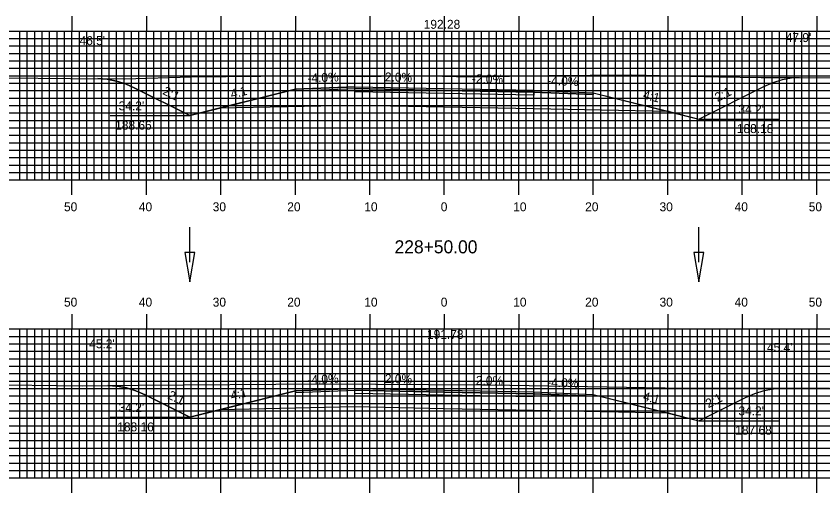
# Model space of a CAD drawing. Extents: x 1798781 to 1799124, y 442591 to 442811.
# Drawn here: x 1798889.5 to 1798997.8, y 442686.7 to 442750.7 of the extents above; entities that cross this region are included whole.
import ezdxf

# ---------------------------------------------------------------- set-up
doc = ezdxf.new("R2010")
doc.units = 0
for name, color, linetype in [('ANNOTATION', 7, 'Continuous'), ('D_Drainage_Ditch_Line', 7, 'Continuous'), ('D_Roadway_Centerline', 7, 'Continuous'), ('D_Roadway_Centerline_Text', 7, 'Continuous'), ('D_Roadway_Edge_Shoulder', 7, 'Continuous'), ('D_Roadway_Edge_TW', 7, 'Continuous'), ('D_Roadway_Pavement', 7, 'Continuous'), ('D_Roadway_SlopeLines', 7, 'Continuous'), ('D_Roadway_SubGrade', 7, 'Continuous'), ('D_Text_Standard', 7, 'Continuous'), ('H_V ANNOTATION', 7, 'Continuous'), ('MAJOR', 7, 'Continuous'), ('MINOR', 7, 'Continuous'), ('PDRAIN', 7, 'Continuous'), ('S_Roadway_Centerline', 7, 'Continuous')]:
    doc.layers.add(name, color=color, linetype=linetype)

msp = doc.modelspace()

# ---------------------------------------------------------------- linework, layer by layer
at = {"layer": 'D_Drainage_Ditch_Line'}
for p, q in [((1798912.81, 442717.63), (1798912.81, 442722.33)), ((1798981.16, 442717.63), (1798981.16, 442722.33))]:
    msp.add_line(p, q, dxfattribs=at)
for points in [[(1798913.47, 442718.94), (1798912.15, 442718.94), (1798912.81, 442715)], [(1798981.81, 442718.94), (1798980.5, 442718.94), (1798981.16, 442715)]]:
    msp.add_lwpolyline(points, close=True, dxfattribs=at)
at = {"layer": 'D_Roadway_Centerline'}
for points in [[(1798900.44, 442742.28), (1798901.69, 442742.19), (1798902.94, 442741.95), (1798904.19, 442741.56), (1798905.44, 442741.01), (1798912.81, 442737.33), (1798916.81, 442738.33), (1798926.98, 442740.87), (1798934.98, 442741.19), (1798946.98, 442740.95), (1798958.98, 442740.71), (1798966.98, 442740.39), (1798977.16, 442737.85), (1798981.16, 442736.85), (1798989.87, 442741.2), (1798991.12, 442741.75), (1798992.37, 442742.14), (1798993.62, 442742.37), (1798994.87, 442742.45)], [(1798901.79, 442701.06), (1798903.04, 442700.99), (1798904.29, 442700.77), (1798905.54, 442700.38), (1798906.79, 442699.84), (1798912.81, 442696.83), (1798916.81, 442697.83), (1798926.98, 442700.37), (1798934.98, 442700.69), (1798946.98, 442700.45), (1798958.98, 442700.21), (1798966.98, 442699.89), (1798977.16, 442697.35), (1798981.16, 442696.35), (1798987.41, 442699.47), (1798988.66, 442700.02), (1798989.91, 442700.41), (1798991.16, 442700.64), (1798992.41, 442700.72)]]:
    msp.add_lwpolyline(points, dxfattribs=at)
at = {"layer": 'D_Roadway_Edge_Shoulder'}
for points in [[(1798934.98, 442741.19), (1798926.98, 442740.87), (1798926.98, 442740.62), (1798934.98, 442740.94)], [(1798958.98, 442740.71), (1798966.98, 442740.39), (1798966.98, 442740.14), (1798958.98, 442740.46)], [(1798934.98, 442700.69), (1798926.98, 442700.37), (1798926.98, 442700.12), (1798934.98, 442700.44)], [(1798958.98, 442700.21), (1798966.98, 442699.89), (1798966.98, 442699.64), (1798958.98, 442699.96)]]:
    msp.add_lwpolyline(points, close=True, dxfattribs=at)
at = {"layer": 'D_Roadway_Edge_TW'}
for points in [[(1798934.98, 442740.94), (1798934.98, 442741.19), (1798946.98, 442740.95), (1798958.98, 442740.71), (1798958.98, 442740.46), (1798946.98, 442740.7)], [(1798934.98, 442700.44), (1798934.98, 442700.69), (1798946.98, 442700.45), (1798958.98, 442700.21), (1798958.98, 442699.96), (1798946.98, 442700.2)]]:
    msp.add_lwpolyline(points, close=True, dxfattribs=at)
at = {"layer": 'D_Roadway_Pavement'}
for points in [[(1798934.98, 442740.52), (1798934.98, 442740.94), (1798946.98, 442740.7), (1798958.98, 442740.46), (1798958.98, 442740.04), (1798946.98, 442740.28)], [(1798934.98, 442700.02), (1798934.98, 442700.44), (1798946.98, 442700.2), (1798958.98, 442699.96), (1798958.98, 442699.54), (1798946.98, 442699.78)]]:
    msp.add_lwpolyline(points, close=True, dxfattribs=at)
at = {"layer": 'D_Roadway_SlopeLines'}
for points in [[(1798912.81, 442737.33), (1798905.44, 442741.01), (1798904.19, 442741.56), (1798902.94, 442741.95), (1798901.69, 442742.19), (1798900.44, 442742.28)], [(1798981.16, 442736.85), (1798989.87, 442741.2), (1798991.12, 442741.75), (1798992.37, 442742.14), (1798993.62, 442742.37), (1798994.87, 442742.45)], [(1798926.98, 442740.87), (1798912.81, 442737.33)], [(1798966.98, 442740.39), (1798981.16, 442736.85)], [(1798912.81, 442696.83), (1798906.79, 442699.84), (1798905.54, 442700.38), (1798904.29, 442700.77), (1798903.04, 442700.99), (1798901.79, 442701.06)], [(1798926.98, 442700.37), (1798912.81, 442696.83)], [(1798981.16, 442696.35), (1798987.41, 442699.47), (1798988.66, 442700.02), (1798989.91, 442700.41), (1798991.16, 442700.64), (1798992.41, 442700.72)], [(1798966.98, 442699.89), (1798981.16, 442696.35)]]:
    msp.add_lwpolyline(points, dxfattribs=at)
at = {"layer": 'D_Roadway_SubGrade'}
for points in [[(1798934.98, 442738.69), (1798916.81, 442738.33), (1798926.98, 442740.87), (1798926.98, 442740.62), (1798934.98, 442740.94), (1798946.98, 442740.7), (1798958.98, 442740.46), (1798966.98, 442740.14), (1798966.98, 442740.39), (1798977.16, 442737.85), (1798958.98, 442738.21), (1798946.98, 442738.45)], [(1798934.98, 442698.19), (1798916.81, 442697.83), (1798926.98, 442700.37), (1798926.98, 442700.12), (1798934.98, 442700.44), (1798946.98, 442700.2), (1798958.98, 442699.96), (1798966.98, 442699.64), (1798966.98, 442699.89), (1798977.16, 442697.35), (1798958.98, 442697.71), (1798946.98, 442697.95)]]:
    msp.add_lwpolyline(points, close=True, dxfattribs=at)
at = {"layer": 'MAJOR'}
for p, q in [((1798896.98, 442750.67), (1798896.98, 442748.67)), ((1798906.98, 442750.67), (1798906.98, 442748.67)), ((1798916.98, 442750.67), (1798916.98, 442748.67)), ((1798926.98, 442750.67), (1798926.98, 442748.67)), ((1798936.98, 442750.67), (1798936.98, 442748.67)), ((1798946.98, 442750.67), (1798946.98, 442748.67)), ((1798956.98, 442750.67), (1798956.98, 442748.67)), ((1798966.98, 442750.67), (1798966.98, 442748.67)), ((1798976.98, 442750.67), (1798976.98, 442748.67)), ((1798986.98, 442750.67), (1798986.98, 442748.67)), ((1798996.98, 442750.67), (1798996.98, 442748.67)), ((1798806.98, 442748.67), (1799086.98, 442748.67)), ((1798806.98, 442748.67), (1799086.98, 442748.67)), ((1798896.98, 442728.67), (1798896.98, 442748.67)), ((1798906.98, 442728.67), (1798906.98, 442748.67)), ((1798916.98, 442728.67), (1798916.98, 442748.67)), ((1798926.98, 442728.67), (1798926.98, 442748.67)), ((1798936.98, 442728.67), (1798936.98, 442748.67)), ((1798946.98, 442728.67), (1798946.98, 442748.67)), ((1798956.98, 442728.67), (1798956.98, 442748.67)), ((1798966.98, 442728.67), (1798966.98, 442748.67)), ((1798976.98, 442728.67), (1798976.98, 442748.67)), ((1798986.98, 442728.67), (1798986.98, 442748.67)), ((1798996.98, 442728.67), (1798996.98, 442748.67)), ((1798806.98, 442743.67), (1799086.98, 442743.67)), ((1798806.98, 442738.67), (1799086.98, 442738.67)), ((1798806.98, 442733.67), (1799086.98, 442733.67)), ((1798806.98, 442728.67), (1799086.98, 442728.67)), ((1798806.98, 442728.67), (1799086.98, 442728.67)), ((1798896.98, 442726.66), (1798896.98, 442728.67)), ((1798906.98, 442726.66), (1798906.98, 442728.67)), ((1798916.98, 442726.66), (1798916.98, 442728.67)), ((1798926.98, 442726.66), (1798926.98, 442728.67)), ((1798936.98, 442726.66), (1798936.98, 442728.67)), ((1798946.98, 442726.66), (1798946.98, 442728.67)), ((1798956.98, 442726.66), (1798956.98, 442728.67)), ((1798966.98, 442726.66), (1798966.98, 442728.67)), ((1798976.98, 442726.66), (1798976.98, 442728.67)), ((1798986.98, 442726.66), (1798986.98, 442728.67)), ((1798996.98, 442726.66), (1798996.98, 442728.67)), ((1798896.98, 442710.67), (1798896.98, 442708.67)), ((1798906.98, 442710.67), (1798906.98, 442708.67)), ((1798916.98, 442710.67), (1798916.98, 442708.67)), ((1798926.98, 442710.67), (1798926.98, 442708.67)), ((1798936.98, 442710.67), (1798936.98, 442708.67)), ((1798946.98, 442710.67), (1798946.98, 442708.67)), ((1798956.98, 442710.67), (1798956.98, 442708.67)), ((1798966.98, 442710.67), (1798966.98, 442708.67)), ((1798976.98, 442710.67), (1798976.98, 442708.67)), ((1798986.98, 442710.67), (1798986.98, 442708.67)), ((1798996.98, 442710.67), (1798996.98, 442708.67)), ((1798806.98, 442708.67), (1799086.98, 442708.67)), ((1798806.98, 442708.67), (1799086.98, 442708.67)), ((1798896.98, 442688.67), (1798896.98, 442708.67)), ((1798906.98, 442688.67), (1798906.98, 442708.67)), ((1798916.98, 442688.67), (1798916.98, 442708.67)), ((1798926.98, 442688.67), (1798926.98, 442708.67)), ((1798936.98, 442688.67), (1798936.98, 442708.67)), ((1798946.98, 442688.67), (1798946.98, 442708.67)), ((1798956.98, 442688.67), (1798956.98, 442708.67)), ((1798966.98, 442688.67), (1798966.98, 442708.67)), ((1798976.98, 442688.67), (1798976.98, 442708.67)), ((1798986.98, 442688.67), (1798986.98, 442708.67)), ((1798996.98, 442688.67), (1798996.98, 442708.67)), ((1798806.98, 442703.67), (1799086.98, 442703.67)), ((1798806.98, 442698.67), (1799086.98, 442698.67)), ((1798806.98, 442693.67), (1799086.98, 442693.67)), ((1798806.98, 442688.67), (1799086.98, 442688.67)), ((1798806.98, 442688.67), (1799086.98, 442688.67)), ((1798896.98, 442686.66), (1798896.98, 442688.67)), ((1798906.98, 442686.66), (1798906.98, 442688.67)), ((1798916.98, 442686.66), (1798916.98, 442688.67)), ((1798926.98, 442686.66), (1798926.98, 442688.67)), ((1798936.98, 442686.66), (1798936.98, 442688.67)), ((1798946.98, 442686.66), (1798946.98, 442688.67)), ((1798956.98, 442686.66), (1798956.98, 442688.67)), ((1798966.98, 442686.66), (1798966.98, 442688.67)), ((1798976.98, 442686.66), (1798976.98, 442688.67)), ((1798986.98, 442686.66), (1798986.98, 442688.67)), ((1798996.98, 442686.66), (1798996.98, 442688.67))]:
    msp.add_line(p, q, dxfattribs=at)
at = {"layer": 'MINOR'}
for p, q in [((1798889.98, 442728.67), (1798889.98, 442748.67)), ((1798890.98, 442728.67), (1798890.98, 442748.67)), ((1798891.98, 442728.67), (1798891.98, 442748.67)), ((1798892.98, 442728.67), (1798892.98, 442748.67)), ((1798893.98, 442728.67), (1798893.98, 442748.67)), ((1798894.98, 442728.67), (1798894.98, 442748.67)), ((1798895.98, 442728.67), (1798895.98, 442748.67)), ((1798897.98, 442728.67), (1798897.98, 442748.67)), ((1798898.98, 442728.67), (1798898.98, 442748.67)), ((1798899.98, 442728.67), (1798899.98, 442748.67)), ((1798900.98, 442728.67), (1798900.98, 442748.67)), ((1798901.98, 442728.67), (1798901.98, 442748.67)), ((1798902.98, 442728.67), (1798902.98, 442748.67)), ((1798903.98, 442728.67), (1798903.98, 442748.67)), ((1798904.98, 442728.67), (1798904.98, 442748.67)), ((1798905.98, 442728.67), (1798905.98, 442748.67)), ((1798907.98, 442728.67), (1798907.98, 442748.67)), ((1798908.98, 442728.67), (1798908.98, 442748.67)), ((1798909.98, 442728.67), (1798909.98, 442748.67)), ((1798910.98, 442728.67), (1798910.98, 442748.67)), ((1798911.98, 442728.67), (1798911.98, 442748.67)), ((1798912.98, 442728.67), (1798912.98, 442748.67)), ((1798913.98, 442728.67), (1798913.98, 442748.67)), ((1798914.98, 442728.67), (1798914.98, 442748.67)), ((1798915.98, 442728.67), (1798915.98, 442748.67)), ((1798917.98, 442728.67), (1798917.98, 442748.67)), ((1798918.98, 442728.67), (1798918.98, 442748.67)), ((1798919.98, 442728.67), (1798919.98, 442748.67)), ((1798920.98, 442728.67), (1798920.98, 442748.67)), ((1798921.98, 442728.67), (1798921.98, 442748.67)), ((1798922.98, 442728.67), (1798922.98, 442748.67)), ((1798923.98, 442728.67), (1798923.98, 442748.67)), ((1798924.98, 442728.67), (1798924.98, 442748.67)), ((1798925.98, 442728.67), (1798925.98, 442748.67)), ((1798927.98, 442728.67), (1798927.98, 442748.67)), ((1798928.98, 442728.67), (1798928.98, 442748.67)), ((1798929.98, 442728.67), (1798929.98, 442748.67)), ((1798930.98, 442728.67), (1798930.98, 442748.67)), ((1798931.98, 442728.67), (1798931.98, 442748.67)), ((1798932.98, 442728.67), (1798932.98, 442748.67)), ((1798933.98, 442728.67), (1798933.98, 442748.67)), ((1798934.98, 442728.67), (1798934.98, 442748.67)), ((1798935.98, 442728.67), (1798935.98, 442748.67)), ((1798937.98, 442728.67), (1798937.98, 442748.67)), ((1798938.98, 442728.67), (1798938.98, 442748.67)), ((1798939.98, 442728.67), (1798939.98, 442748.67)), ((1798940.98, 442728.67), (1798940.98, 442748.67)), ((1798941.98, 442728.67), (1798941.98, 442748.67)), ((1798942.98, 442728.67), (1798942.98, 442748.67)), ((1798943.98, 442728.67), (1798943.98, 442748.67)), ((1798944.98, 442728.67), (1798944.98, 442748.67)), ((1798945.98, 442728.67), (1798945.98, 442748.67)), ((1798947.98, 442728.67), (1798947.98, 442748.67)), ((1798948.98, 442728.67), (1798948.98, 442748.67)), ((1798949.98, 442728.67), (1798949.98, 442748.67)), ((1798950.98, 442728.67), (1798950.98, 442748.67)), ((1798951.98, 442728.67), (1798951.98, 442748.67)), ((1798952.98, 442728.67), (1798952.98, 442748.67)), ((1798953.98, 442728.67), (1798953.98, 442748.67)), ((1798954.98, 442728.67), (1798954.98, 442748.67)), ((1798955.98, 442728.67), (1798955.98, 442748.67)), ((1798957.98, 442728.67), (1798957.98, 442748.67)), ((1798958.98, 442728.67), (1798958.98, 442748.67)), ((1798959.98, 442728.67), (1798959.98, 442748.67)), ((1798960.98, 442728.67), (1798960.98, 442748.67)), ((1798961.98, 442728.67), (1798961.98, 442748.67)), ((1798962.98, 442728.67), (1798962.98, 442748.67)), ((1798963.98, 442728.67), (1798963.98, 442748.67)), ((1798964.98, 442728.67), (1798964.98, 442748.67)), ((1798965.98, 442728.67), (1798965.98, 442748.67)), ((1798967.98, 442728.67), (1798967.98, 442748.67)), ((1798968.98, 442728.67), (1798968.98, 442748.67)), ((1798969.98, 442728.67), (1798969.98, 442748.67)), ((1798970.98, 442728.67), (1798970.98, 442748.67)), ((1798971.98, 442728.67), (1798971.98, 442748.67)), ((1798972.98, 442728.67), (1798972.98, 442748.67)), ((1798973.98, 442728.67), (1798973.98, 442748.67)), ((1798974.98, 442728.67), (1798974.98, 442748.67)), ((1798975.98, 442728.67), (1798975.98, 442748.67)), ((1798977.98, 442728.67), (1798977.98, 442748.67)), ((1798978.98, 442728.67), (1798978.98, 442748.67)), ((1798979.98, 442728.67), (1798979.98, 442748.67)), ((1798980.98, 442728.67), (1798980.98, 442748.67)), ((1798981.98, 442728.67), (1798981.98, 442748.67)), ((1798982.98, 442728.67), (1798982.98, 442748.67)), ((1798983.98, 442728.67), (1798983.98, 442748.67)), ((1798984.98, 442728.67), (1798984.98, 442748.67)), ((1798985.98, 442728.67), (1798985.98, 442748.67)), ((1798987.98, 442728.67), (1798987.98, 442748.67)), ((1798988.98, 442728.67), (1798988.98, 442748.67)), ((1798989.98, 442728.67), (1798989.98, 442748.67)), ((1798990.98, 442728.67), (1798990.98, 442748.67)), ((1798991.98, 442728.67), (1798991.98, 442748.67)), ((1798992.98, 442728.67), (1798992.98, 442748.67)), ((1798993.98, 442728.67), (1798993.98, 442748.67)), ((1798994.98, 442728.67), (1798994.98, 442748.67)), ((1798995.98, 442728.67), (1798995.98, 442748.67)), ((1798806.98, 442747.67), (1799086.98, 442747.67)), ((1798806.98, 442746.67), (1799086.98, 442746.67)), ((1798806.98, 442745.67), (1799086.98, 442745.67)), ((1798806.98, 442744.67), (1799086.98, 442744.67)), ((1798806.98, 442742.67), (1799086.98, 442742.67)), ((1798806.98, 442741.67), (1799086.98, 442741.67)), ((1798806.98, 442740.67), (1799086.98, 442740.67)), ((1798806.98, 442739.67), (1799086.98, 442739.67)), ((1798806.98, 442737.67), (1799086.98, 442737.67)), ((1798806.98, 442736.67), (1799086.98, 442736.67)), ((1798806.98, 442735.67), (1799086.98, 442735.67)), ((1798806.98, 442734.67), (1799086.98, 442734.67)), ((1798806.98, 442732.67), (1799086.98, 442732.67)), ((1798806.98, 442731.67), (1799086.98, 442731.67)), ((1798806.98, 442730.67), (1799086.98, 442730.67)), ((1798806.98, 442729.67), (1799086.98, 442729.67)), ((1798889.98, 442688.67), (1798889.98, 442708.67)), ((1798890.98, 442688.67), (1798890.98, 442708.67)), ((1798891.98, 442688.67), (1798891.98, 442708.67)), ((1798892.98, 442688.67), (1798892.98, 442708.67)), ((1798893.98, 442688.67), (1798893.98, 442708.67)), ((1798894.98, 442688.67), (1798894.98, 442708.67)), ((1798895.98, 442688.67), (1798895.98, 442708.67)), ((1798897.98, 442688.67), (1798897.98, 442708.67)), ((1798898.98, 442688.67), (1798898.98, 442708.67)), ((1798899.98, 442688.67), (1798899.98, 442708.67)), ((1798900.98, 442688.67), (1798900.98, 442708.67)), ((1798901.98, 442688.67), (1798901.98, 442708.67)), ((1798902.98, 442688.67), (1798902.98, 442708.67)), ((1798903.98, 442688.67), (1798903.98, 442708.67)), ((1798904.98, 442688.67), (1798904.98, 442708.67)), ((1798905.98, 442688.67), (1798905.98, 442708.67)), ((1798907.98, 442688.67), (1798907.98, 442708.67)), ((1798908.98, 442688.67), (1798908.98, 442708.67)), ((1798909.98, 442688.67), (1798909.98, 442708.67)), ((1798910.98, 442688.67), (1798910.98, 442708.67)), ((1798911.98, 442688.67), (1798911.98, 442708.67)), ((1798912.98, 442688.67), (1798912.98, 442708.67)), ((1798913.98, 442688.67), (1798913.98, 442708.67)), ((1798914.98, 442688.67), (1798914.98, 442708.67)), ((1798915.98, 442688.67), (1798915.98, 442708.67)), ((1798917.98, 442688.67), (1798917.98, 442708.67)), ((1798918.98, 442688.67), (1798918.98, 442708.67)), ((1798919.98, 442688.67), (1798919.98, 442708.67)), ((1798920.98, 442688.67), (1798920.98, 442708.67)), ((1798921.98, 442688.67), (1798921.98, 442708.67)), ((1798922.98, 442688.67), (1798922.98, 442708.67)), ((1798923.98, 442688.67), (1798923.98, 442708.67)), ((1798924.98, 442688.67), (1798924.98, 442708.67)), ((1798925.98, 442688.67), (1798925.98, 442708.67)), ((1798927.98, 442688.67), (1798927.98, 442708.67)), ((1798928.98, 442688.67), (1798928.98, 442708.67)), ((1798929.98, 442688.67), (1798929.98, 442708.67)), ((1798930.98, 442688.67), (1798930.98, 442708.67)), ((1798931.98, 442688.67), (1798931.98, 442708.67)), ((1798932.98, 442688.67), (1798932.98, 442708.67)), ((1798933.98, 442688.67), (1798933.98, 442708.67)), ((1798934.98, 442688.67), (1798934.98, 442708.67)), ((1798935.98, 442688.67), (1798935.98, 442708.67)), ((1798937.98, 442688.67), (1798937.98, 442708.67)), ((1798938.98, 442688.67), (1798938.98, 442708.67)), ((1798939.98, 442688.67), (1798939.98, 442708.67)), ((1798940.98, 442688.67), (1798940.98, 442708.67)), ((1798941.98, 442688.67), (1798941.98, 442708.67)), ((1798942.98, 442688.67), (1798942.98, 442708.67)), ((1798943.98, 442688.67), (1798943.98, 442708.67)), ((1798944.98, 442688.67), (1798944.98, 442708.67)), ((1798945.98, 442688.67), (1798945.98, 442708.67)), ((1798947.98, 442688.67), (1798947.98, 442708.67)), ((1798948.98, 442688.67), (1798948.98, 442708.67)), ((1798949.98, 442688.67), (1798949.98, 442708.67)), ((1798950.98, 442688.67), (1798950.98, 442708.67)), ((1798951.98, 442688.67), (1798951.98, 442708.67)), ((1798952.98, 442688.67), (1798952.98, 442708.67)), ((1798953.98, 442688.67), (1798953.98, 442708.67)), ((1798954.98, 442688.67), (1798954.98, 442708.67)), ((1798955.98, 442688.67), (1798955.98, 442708.67)), ((1798957.98, 442688.67), (1798957.98, 442708.67)), ((1798958.98, 442688.67), (1798958.98, 442708.67)), ((1798959.98, 442688.67), (1798959.98, 442708.67)), ((1798960.98, 442688.67), (1798960.98, 442708.67)), ((1798961.98, 442688.67), (1798961.98, 442708.67)), ((1798962.98, 442688.67), (1798962.98, 442708.67)), ((1798963.98, 442688.67), (1798963.98, 442708.67)), ((1798964.98, 442688.67), (1798964.98, 442708.67)), ((1798965.98, 442688.67), (1798965.98, 442708.67)), ((1798967.98, 442688.67), (1798967.98, 442708.67)), ((1798968.98, 442688.67), (1798968.98, 442708.67)), ((1798969.98, 442688.67), (1798969.98, 442708.67)), ((1798970.98, 442688.67), (1798970.98, 442708.67)), ((1798971.98, 442688.67), (1798971.98, 442708.67)), ((1798972.98, 442688.67), (1798972.98, 442708.67)), ((1798973.98, 442688.67), (1798973.98, 442708.67)), ((1798974.98, 442688.67), (1798974.98, 442708.67)), ((1798975.98, 442688.67), (1798975.98, 442708.67)), ((1798977.98, 442688.67), (1798977.98, 442708.67)), ((1798978.98, 442688.67), (1798978.98, 442708.67)), ((1798979.98, 442688.67), (1798979.98, 442708.67)), ((1798980.98, 442688.67), (1798980.98, 442708.67)), ((1798981.98, 442688.67), (1798981.98, 442708.67)), ((1798982.98, 442688.67), (1798982.98, 442708.67)), ((1798983.98, 442688.67), (1798983.98, 442708.67)), ((1798984.98, 442688.67), (1798984.98, 442708.67)), ((1798985.98, 442688.67), (1798985.98, 442708.67)), ((1798987.98, 442688.67), (1798987.98, 442708.67)), ((1798988.98, 442688.67), (1798988.98, 442708.67)), ((1798989.98, 442688.67), (1798989.98, 442708.67)), ((1798990.98, 442688.67), (1798990.98, 442708.67)), ((1798991.98, 442688.67), (1798991.98, 442708.67)), ((1798992.98, 442688.67), (1798992.98, 442708.67)), ((1798993.98, 442688.67), (1798993.98, 442708.67)), ((1798994.98, 442688.67), (1798994.98, 442708.67)), ((1798995.98, 442688.67), (1798995.98, 442708.67)), ((1798806.98, 442707.67), (1799086.98, 442707.67)), ((1798806.98, 442706.67), (1799086.98, 442706.67)), ((1798806.98, 442705.67), (1799086.98, 442705.67)), ((1798806.98, 442704.67), (1799086.98, 442704.67)), ((1798806.98, 442702.67), (1799086.98, 442702.67)), ((1798806.98, 442701.67), (1799086.98, 442701.67)), ((1798806.98, 442700.67), (1799086.98, 442700.67)), ((1798806.98, 442699.67), (1799086.98, 442699.67)), ((1798806.98, 442697.67), (1799086.98, 442697.67)), ((1798806.98, 442696.67), (1799086.98, 442696.67)), ((1798806.98, 442695.67), (1799086.98, 442695.67)), ((1798806.98, 442694.67), (1799086.98, 442694.67)), ((1798806.98, 442692.67), (1799086.98, 442692.67)), ((1798806.98, 442691.67), (1799086.98, 442691.67)), ((1798806.98, 442690.67), (1799086.98, 442690.67)), ((1798806.98, 442689.67), (1799086.98, 442689.67))]:
    msp.add_line(p, q, dxfattribs=at)
at = {"layer": 'PDRAIN'}
for p, q in [((1798902.09, 442737.33), (1798912.81, 442737.33)), ((1798981.16, 442736.85), (1798991.93, 442736.85)), ((1798902.09, 442696.83), (1798912.81, 442696.83)), ((1798981.16, 442696.35), (1798991.93, 442696.35))]:
    msp.add_line(p, q, dxfattribs=at)
at = {"layer": 'S_Roadway_Centerline'}
for points in [[(1798888.06, 442742.38), (1798896.78, 442742.31), (1798904.06, 442742.25), (1798912.99, 442742.51), (1798927.06, 442742.66), (1798936.27, 442742.57), (1798942.99, 442742.7), (1798950.5, 442742.54), (1798961.02, 442742.68), (1798972.12, 442742.78), (1798983.82, 442742.54), (1798989.52, 442742.45), (1798994.67, 442742.45), (1799007.61, 442742.39)], [(1798884.74, 442701.2), (1798898.44, 442701.03), (1798905.93, 442701.1), (1798930.47, 442701.32), (1798930.69, 442701.32), (1798951.92, 442701.16), (1798952.52, 442701.16), (1798953.18, 442701.15), (1798976.63, 442700.76), (1798979.73, 442700.72), (1798996.53, 442700.72), (1798998.64, 442700.76)]]:
    msp.add_lwpolyline(points, dxfattribs=at)

# ---------------------------------------------------------------- texts
at = {"layer": 'ANNOTATION'}
for s, rotation, p in [('-4.0%', 2.2906, (1798928.62, 442741.74)), ('2.0%', 358.8542, (1798938.99, 442741.91)), ('-2.0%', 358.8542, (1798950.67, 442741.68)), ('-4.0%', 357.7094, (1798960.78, 442741.44)), ('2:1', 333.4349, (1798909.06, 442740.24)), ('4:1', 14.0362, (1798918.43, 442739.59)), ('4:1', 345.9638, (1798973.58, 442739.6)), ('2:1', 26.5651, (1798983.66, 442739.13)), ('-4.0%', 2.2906, (1798928.62, 442701.24)), ('2.0%', 358.8542, (1798938.99, 442701.41)), ('-2.0%', 358.8542, (1798950.67, 442701.18)), ('-4.0%', 357.7094, (1798960.78, 442700.94)), ('2:1', 333.4349, (1798909.73, 442699.4)), ('4:1', 14.0362, (1798918.43, 442699.09)), ('4:1', 345.9638, (1798973.58, 442699.1)), ('2:1', 26.5651, (1798982.43, 442698.02))]:
    msp.add_text(s, height=1.2, rotation=rotation, dxfattribs=at).set_placement(p)
for s, p in [("34.2'", (1798903.25, 442738.02)), ("34.2'", (1798986.47, 442737.57)), ('188.66', (1798902.78, 442735.42)), ('188.18', (1798986.26, 442734.97)), ("34.2'", (1798903.25, 442697.52)), ("34.2'", (1798986.47, 442697.07)), ('188.16', (1798903.06, 442694.92)), ('187.68', (1798986.04, 442694.47))]:
    msp.add_text(s, height=1.2, dxfattribs=at).set_placement(p)
at = {"layer": 'D_Roadway_Centerline'}
for s, p in [('C', (1798946.98, 442740.95)), ('L', (1798946.98, 442740.94)), ('C', (1798946.98, 442700.45)), ('L', (1798946.98, 442700.44))]:
    msp.add_text(s, height=0.0146, dxfattribs=at).set_placement(p)
at = {"layer": 'D_Roadway_Centerline_Text'}
for s, p in [('192.28', (1798944.21, 442748.97)), ('191.78', (1798944.65, 442707.34))]:
    msp.add_text(s, height=1.2, dxfattribs=at).set_placement(p)
at = {"layer": 'D_Text_Standard'}
for s, p in [("46.5'", (1798898, 442746.78)), ("47.9'", (1798992.83, 442747.19)), ("45.2'", (1798899.29, 442706.08)), ("45.4'", (1798990.3, 442705.59))]:
    msp.add_text(s, height=1.2, dxfattribs=at).set_placement(p)
at = {"layer": 'H_V ANNOTATION'}
for s, height, p in [('50', 1.2, (1798895.91, 442724.47)), ('40', 1.2, (1798905.96, 442724.47)), ('30', 1.2, (1798915.88, 442724.47)), ('20', 1.2, (1798925.89, 442724.47)), ('10', 1.2, (1798936.23, 442724.47)), ('0', 1.2, (1798946.5, 442724.47)), ('10', 1.2, (1798956.23, 442724.47)), ('20', 1.2, (1798965.89, 442724.47)), ('30', 1.2, (1798975.88, 442724.47)), ('40', 1.2, (1798985.96, 442724.47)), ('50', 1.2, (1798995.91, 442724.47)), ('228+50.00', 1.75, (1798940.3, 442718.82)), ('50', 1.2, (1798895.91, 442711.67)), ('40', 1.2, (1798905.96, 442711.67)), ('30', 1.2, (1798915.88, 442711.67)), ('20', 1.2, (1798925.89, 442711.67)), ('10', 1.2, (1798936.23, 442711.67)), ('0', 1.2, (1798946.5, 442711.67)), ('10', 1.2, (1798956.23, 442711.67)), ('20', 1.2, (1798965.89, 442711.67)), ('30', 1.2, (1798975.88, 442711.67)), ('40', 1.2, (1798985.96, 442711.67)), ('50', 1.2, (1798995.91, 442711.67))]:
    msp.add_text(s, height=height, dxfattribs=at).set_placement(p)

doc.saveas('drawing.dxf')
